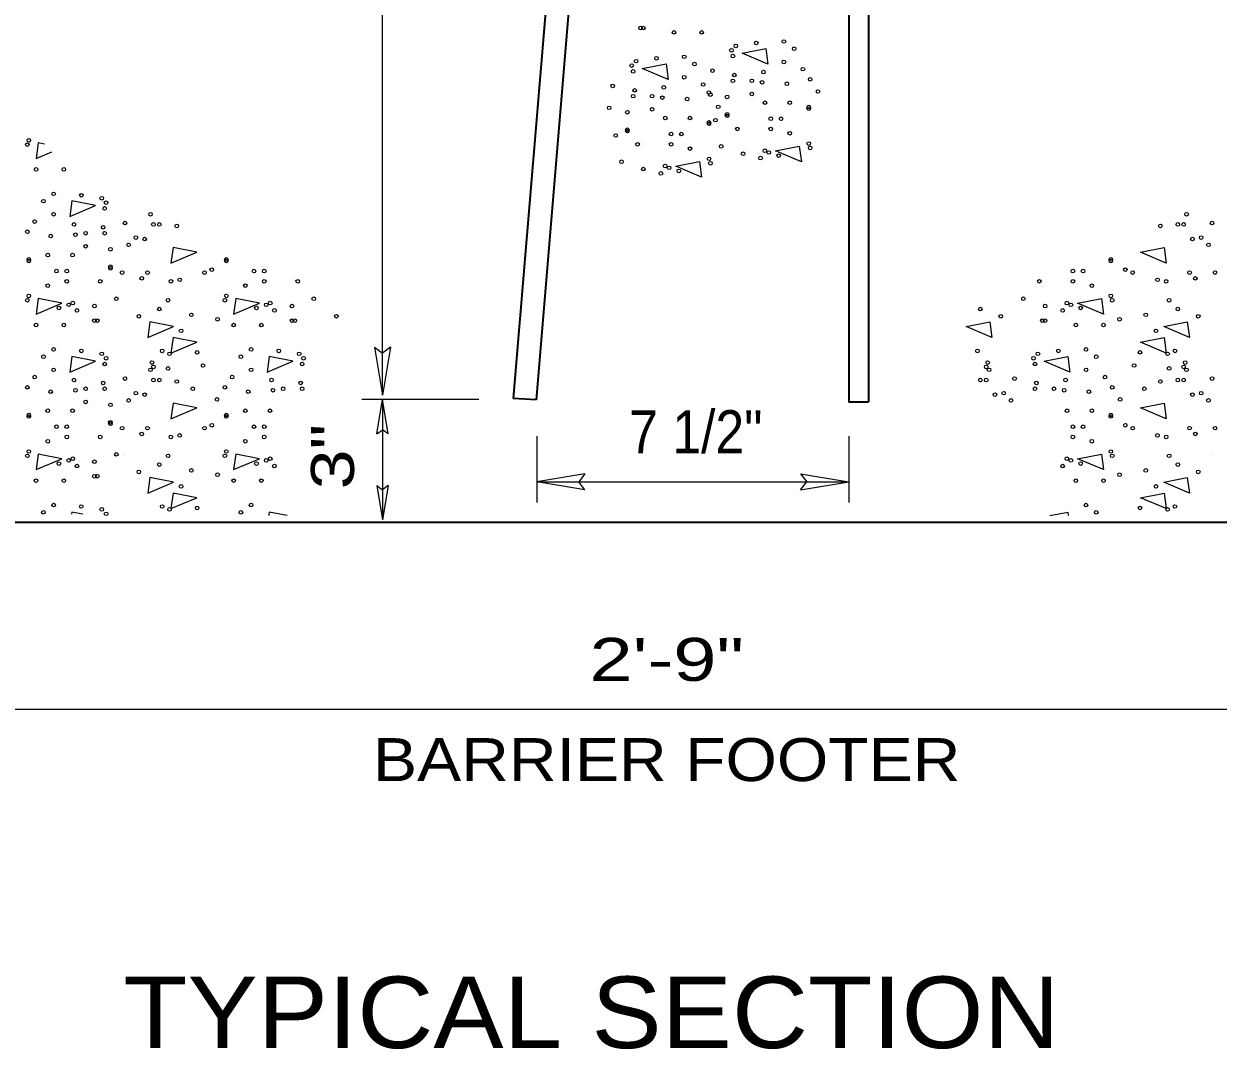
# Model space of a CAD drawing. Extents: x -16.43 to -9.36, y -8.57 to 1.26.
# Drawn here: x -14.571 to -12.904, y -3.734 to -2.302 of the extents above; entities that cross this region are included whole.
import ezdxf
from ezdxf.enums import TextEntityAlignment as Align

# ---------------------------------------------------------------- set-up
doc = ezdxf.new("R2010")
doc.units = 0
doc.header["$LTSCALE"] = 0.024
for name, color, linetype, lineweight in [('1', 7, 'Continuous', 35), ('10', 7, 'Continuous', 13), ('12', 7, 'Continuous', 53), ('6', 7, 'Continuous', 13)]:
    doc.layers.add(name, color=color, linetype=linetype, lineweight=lineweight)

msp = doc.modelspace()

# ---------------------------------------------------------------- linework, layer by layer
at = {"layer": '1'}
for p, q in [((-13.392, 0.00867), (-13.392, -2.83033)), ((-13.69975, -0.56375), (-13.88817, -2.82583)), ((-13.66625, -0.552), (-13.85583, -2.82733)), ((-13.85583, -2.82733), (-13.88817, -2.82583)), ((-14.66667, -2.99817), (-12.69033, -2.99817))]:
    msp.add_line(p, q, dxfattribs=at)
msp.add_lwpolyline([(-13.41917, 0.01217), (-13.41917, -2.83033), (-13.392, -2.83033)], dxfattribs=at)
at = {"layer": '10'}
for p, q in [((-14.0705, -2.82117), (-14.0705, -1.52417)), ((-14.08167, -2.75383), (-14.0705, -2.82117)), ((-14.08167, -2.75383), (-14.0705, -2.76233)), ((-14.05933, -2.75383), (-14.0705, -2.82117)), ((-14.05933, -2.75383), (-14.0705, -2.76233)), ((-13.93617, -2.82717), (-14.09933, -2.82717)), ((-14.0785, -2.87517), (-14.0705, -2.82717)), ((-14.0705, -2.82717), (-14.0705, -2.99517)), ((-14.0625, -2.87517), (-14.0705, -2.82717)), ((-14.0785, -2.87517), (-14.0705, -2.86917)), ((-14.0625, -2.87517), (-14.0705, -2.86917)), ((-13.85517, -2.87833), (-13.85517, -2.97083)), ((-13.4195, -2.87833), (-13.4195, -2.97083)), ((-13.788, -2.93083), (-13.85517, -2.942)), ((-13.788, -2.93083), (-13.79633, -2.942)), ((-13.48667, -2.93083), (-13.4195, -2.942)), ((-13.48667, -2.93083), (-13.47817, -2.942)), ((-14.0785, -2.94717), (-14.0705, -2.99517)), ((-14.0785, -2.94717), (-14.0705, -2.95317)), ((-14.0625, -2.94717), (-14.0705, -2.99517)), ((-14.0625, -2.94717), (-14.0705, -2.95317)), ((-13.85517, -2.942), (-13.4195, -2.942)), ((-13.788, -2.95317), (-13.85517, -2.942)), ((-13.788, -2.95317), (-13.79633, -2.942)), ((-13.48667, -2.95317), (-13.4195, -2.942)), ((-13.48667, -2.95317), (-13.47817, -2.942)), ((-12.69017, -3.26017), (-14.66583, -3.26017))]:
    msp.add_line(p, q, dxfattribs=at)
at = {"layer": '6'}
for points in [[(-13.5685, -2.34317), (-13.53533, -2.33667), (-13.5325, -2.3585)], [(-13.70783, -2.3645), (-13.67467, -2.358), (-13.67183, -2.37983)], [(-13.52167, -2.4795), (-13.48867, -2.473), (-13.48567, -2.49483)], [(-13.661, -2.50083), (-13.62783, -2.49433), (-13.625, -2.51633)], [(-14.4715, -2.556), (-14.5045, -2.5495), (-14.5075, -2.57133)], [(-14.33, -2.621), (-14.36317, -2.61467), (-14.366, -2.6365)], [(-13.01217, -2.621), (-12.97917, -2.61467), (-12.97633, -2.6365)], [(-14.51833, -2.69233), (-14.55133, -2.68583), (-14.55417, -2.70767)], [(-14.2425, -2.69233), (-14.2755, -2.68583), (-14.2785, -2.70767)], [(-13.09983, -2.69233), (-13.06667, -2.68583), (-13.06383, -2.70767)], [(-14.36267, -2.725), (-14.39567, -2.7185), (-14.3985, -2.74033)], [(-13.2555, -2.725), (-13.22233, -2.7185), (-13.2195, -2.74033)], [(-12.97967, -2.725), (-12.94667, -2.7185), (-12.94367, -2.74033)], [(-14.33, -2.74683), (-14.36317, -2.74033), (-14.366, -2.76217)], [(-13.01217, -2.74683), (-12.97917, -2.74033), (-12.97633, -2.76217)], [(-14.4715, -2.77333), (-14.5045, -2.76683), (-14.5075, -2.78867)], [(-14.19567, -2.77333), (-14.22883, -2.76683), (-14.23167, -2.78867)], [(-13.14667, -2.77333), (-13.1135, -2.76683), (-13.11067, -2.78867)], [(-14.33, -2.8385), (-14.36317, -2.832), (-14.366, -2.85383)], [(-13.01217, -2.8385), (-12.97917, -2.832), (-12.97633, -2.85383)], [(-14.51833, -2.90967), (-14.55133, -2.90317), (-14.55417, -2.925)], [(-14.2425, -2.90967), (-14.2755, -2.90317), (-14.2785, -2.925)], [(-13.09983, -2.90967), (-13.06667, -2.90317), (-13.06383, -2.925)], [(-14.36267, -2.94233), (-14.39567, -2.93583), (-14.3985, -2.95767)], [(-12.97967, -2.94233), (-12.94667, -2.93583), (-12.94367, -2.95767)], [(-14.33, -2.96417), (-14.36317, -2.95767), (-14.366, -2.9795)], [(-13.01217, -2.96417), (-12.97917, -2.95767), (-12.97633, -2.9795)]]:
    msp.add_lwpolyline(points, close=True, dxfattribs=at)
for points in [[(-14.54267, -2.47017), (-14.55133, -2.4685), (-14.55417, -2.49033), (-14.53233, -2.481)], [(-14.489, -2.98717), (-14.5045, -2.98417), (-14.505, -2.98717)], [(-14.20383, -2.989), (-14.22883, -2.98417), (-14.22933, -2.98883)], [(-13.1385, -2.989), (-13.1135, -2.98417), (-13.113, -2.98883)]]:
    msp.add_lwpolyline(points, dxfattribs=at)
for centre in [(-13.71035, -2.3081), (-13.70631, -2.3081), (-13.66354, -2.31418), (-13.62486, -2.31418), (-13.57721, -2.33302), (-13.54873, -2.32894), (-13.51004, -2.3269), (-13.49576, -2.3371), (-13.68799, -2.35034), (-13.6493, -2.3483), (-13.58333, -2.33914), (-13.58129, -2.34726), (-13.72259, -2.36055), (-13.72055, -2.36867), (-13.71647, -2.35442), (-13.63502, -2.3585), (-13.60977, -2.36763), (-13.53852, -2.36967), (-13.51004, -2.35542), (-13.48355, -2.36559), (-13.6493, -2.37683), (-13.62282, -2.38699), (-13.58129, -2.38187), (-13.57925, -2.37375), (-13.55481, -2.38187), (-13.54056, -2.38391), (-13.50596, -2.38595), (-13.47339, -2.37983), (-13.74904, -2.38903), (-13.72055, -2.40327), (-13.71851, -2.39515), (-13.69407, -2.40327), (-13.67779, -2.39107), (-13.61482, -2.39815), (-13.61266, -2.40123), (-13.55481, -2.40019), (-13.46247, -2.39675), (-13.75408, -2.41955), (-13.67983, -2.40531), (-13.64522, -2.40735), (-13.60173, -2.41815), (-13.58941, -2.40427), (-13.53648, -2.41243), (-13.50188, -2.41243), (-13.47539, -2.41851), (-13.47539, -2.42055), (-13.72867, -2.42568), (-13.69407, -2.42159), (-13.67575, -2.43384), (-13.64114, -2.43384), (-13.60569, -2.43684), (-13.58941, -2.42872), (-13.58941, -2.43076), (-13.52836, -2.4348), (-13.51408, -2.4348), (-13.72867, -2.45012), (-13.72867, -2.45216), (-13.61466, -2.43992), (-13.61466, -2.44196), (-13.57517, -2.44908), (-13.52836, -2.44908), (-14.56455, -2.46492), (-13.74496, -2.45824), (-13.71443, -2.47048), (-13.66762, -2.4562), (-13.66762, -2.47048), (-13.65334, -2.4562), (-13.50188, -2.45516), (-13.47539, -2.46944), (-14.56655, -2.471), (-13.64114, -2.47656), (-13.59757, -2.47348), (-13.56705, -2.48368), (-13.53672, -2.47952), (-13.53108, -2.48196), (-13.51744, -2.48633), (-13.47339, -2.47552), (-13.73684, -2.49489), (-13.67599, -2.50093), (-13.67034, -2.50337), (-13.61466, -2.49085), (-13.61266, -2.49693), (-13.5426, -2.48977), (-14.55435, -2.50561), (-14.51566, -2.50561), (-13.70631, -2.50509), (-13.68187, -2.51117), (-13.6567, -2.50773), (-14.54419, -2.54994), (-14.52991, -2.53973), (-14.49122, -2.54177), (-14.46273, -2.54585), (-14.45661, -2.55198), (-14.52991, -2.56826), (-14.45865, -2.5601), (-14.3946, -2.56826), (-12.94767, -2.56826), (-14.55639, -2.57842), (-14.50142, -2.5825), (-14.46069, -2.58658), (-14.43017, -2.58046), (-14.39052, -2.5825), (-14.38236, -2.5825), (-14.35796, -2.58454), (-12.98431, -2.58454), (-12.95991, -2.5825), (-12.95175, -2.5825), (-12.9121, -2.58046), (-14.56655, -2.59266), (-14.53399, -2.59878), (-14.49938, -2.59674), (-14.48514, -2.5947), (-14.45865, -2.5947), (-14.41497, -2.60082), (-14.40273, -2.60286), (-12.93955, -2.60286), (-12.92731, -2.60082), (-14.48514, -2.61303), (-14.45053, -2.61711), (-14.42513, -2.61099), (-12.91714, -2.61099), (-14.56455, -2.63135), (-14.56455, -2.63339), (-14.53807, -2.62527), (-14.50346, -2.62527), (-14.28875, -2.63135), (-14.28875, -2.63339), (-13.05353, -2.63135), (-13.05353, -2.63339), (-14.52586, -2.64763), (-14.51158, -2.64763), (-14.45053, -2.64155), (-14.45053, -2.64359), (-14.43425, -2.64967), (-14.39868, -2.64967), (-14.31927, -2.64967), (-14.30907, -2.64563), (-14.25006, -2.64763), (-14.23578, -2.64763), (-13.10649, -2.64763), (-13.09221, -2.64763), (-13.0332, -2.64563), (-13.023, -2.64967), (-12.94359, -2.64967), (-12.90802, -2.64967), (-14.53807, -2.66799), (-14.51158, -2.66191), (-14.46478, -2.66191), (-14.40681, -2.65783), (-14.36608, -2.66191), (-14.35388, -2.65987), (-14.26226, -2.66799), (-14.23578, -2.66191), (-14.18897, -2.66191), (-13.1533, -2.66191), (-13.10649, -2.66191), (-13.08001, -2.66799), (-12.9884, -2.65987), (-12.97619, -2.66191), (-12.93547, -2.65783), (-14.56455, -2.68228), (-14.44237, -2.68632), (-14.28875, -2.68228), (-14.16657, -2.68632), (-13.17571, -2.68632), (-13.05353, -2.68228), (-14.56655, -2.68836), (-14.5225, -2.69916), (-14.50886, -2.6948), (-14.50322, -2.69236), (-14.49734, -2.7026), (-14.4729, -2.69652), (-14.38236, -2.7006), (-14.37016, -2.68836), (-14.29075, -2.68836), (-14.2467, -2.69916), (-14.23306, -2.6948), (-14.22742, -2.69236), (-14.22154, -2.7026), (-14.19709, -2.69652), (-13.23572, -2.7006), (-13.14518, -2.69652), (-13.12074, -2.7026), (-13.11486, -2.69236), (-13.10921, -2.6948), (-13.09557, -2.69916), (-13.05153, -2.68836), (-12.97211, -2.68836), (-12.95991, -2.7006), (-14.4729, -2.71688), (-14.46886, -2.71688), (-14.41089, -2.71076), (-14.33759, -2.70872), (-14.30095, -2.71484), (-14.19709, -2.71688), (-14.19305, -2.71688), (-14.13508, -2.71076), (-13.20719, -2.71076), (-13.14922, -2.71688), (-13.14518, -2.71688), (-13.04132, -2.71484), (-13.00468, -2.70872), (-12.93139, -2.71076), (-14.55435, -2.72296), (-14.51566, -2.72296), (-14.35184, -2.73112), (-14.27855, -2.72296), (-14.23986, -2.72296), (-13.10241, -2.72296), (-13.06373, -2.72296), (-12.99044, -2.73112), (-14.54419, -2.76729), (-14.52991, -2.75709), (-14.49122, -2.75913), (-14.46273, -2.76321), (-14.45661, -2.76933), (-14.37832, -2.75913), (-14.36812, -2.76321), (-14.32943, -2.76117), (-14.26838, -2.76729), (-14.2541, -2.75709), (-14.21542, -2.75913), (-14.18693, -2.76321), (-14.18081, -2.76933), (-13.23976, -2.75913), (-13.16146, -2.76933), (-13.15534, -2.76321), (-13.12686, -2.75913), (-13.08817, -2.75709), (-13.07389, -2.76729), (-13.01284, -2.76117), (-12.97415, -2.76321), (-12.96395, -2.75913), (-14.52991, -2.78561), (-14.45865, -2.77745), (-14.3946, -2.78561), (-14.39256, -2.77541), (-14.39052, -2.78153), (-14.37016, -2.78357), (-14.32131, -2.77949), (-14.2541, -2.78561), (-14.18285, -2.77745), (-13.22755, -2.78153), (-13.22551, -2.77541), (-13.22347, -2.78561), (-13.15942, -2.77745), (-13.08817, -2.78561), (-13.02096, -2.77949), (-12.97211, -2.78357), (-12.95175, -2.78153), (-12.94971, -2.77541), (-12.94767, -2.78561), (-14.55639, -2.79577), (-14.50142, -2.79986), (-14.46069, -2.80394), (-14.43017, -2.79782), (-14.39052, -2.79986), (-14.38236, -2.79986), (-14.35796, -2.8019), (-14.28059, -2.79577), (-14.22562, -2.79986), (-14.18489, -2.80394), (-13.23572, -2.79986), (-13.22755, -2.79986), (-13.18791, -2.79782), (-13.15738, -2.80394), (-13.11666, -2.79986), (-13.06169, -2.79577), (-12.98431, -2.8019), (-12.95991, -2.79986), (-12.95175, -2.79986), (-12.9121, -2.79782), (-14.56655, -2.81002), (-14.53399, -2.81614), (-14.49938, -2.8141), (-14.48514, -2.81206), (-14.45865, -2.81206), (-14.41497, -2.81818), (-14.40273, -2.82022), (-14.33555, -2.81206), (-14.29075, -2.81002), (-14.25818, -2.81614), (-14.22358, -2.8141), (-14.20933, -2.81206), (-14.18285, -2.81206), (-13.21535, -2.82022), (-13.20311, -2.81818), (-13.15942, -2.81206), (-13.13294, -2.81206), (-13.1187, -2.8141), (-13.08409, -2.81614), (-13.05153, -2.81002), (-13.00672, -2.81206), (-12.93955, -2.82022), (-12.92731, -2.81818), (-14.48514, -2.83038), (-14.45053, -2.83446), (-14.42513, -2.82834), (-14.30167, -2.82694), (-13.19295, -2.82834), (-13.0406, -2.82694), (-12.91714, -2.82834), (-14.56455, -2.8487), (-14.56455, -2.85074), (-14.53807, -2.84262), (-14.50346, -2.84262), (-14.28875, -2.8487), (-14.28875, -2.85074), (-14.26226, -2.84262), (-14.22766, -2.84262), (-13.11462, -2.84262), (-13.08001, -2.84262), (-13.05353, -2.8487), (-13.05353, -2.85074), (-14.52586, -2.86499), (-14.51158, -2.86499), (-14.45053, -2.8589), (-14.45053, -2.86095), (-14.43425, -2.86703), (-14.39868, -2.86703), (-14.31927, -2.86703), (-14.30907, -2.86299), (-14.25006, -2.86499), (-14.23578, -2.86499), (-13.10649, -2.86499), (-13.09221, -2.86499), (-13.0332, -2.86299), (-13.023, -2.86703), (-12.94359, -2.86703), (-12.90802, -2.86703), (-14.53807, -2.88535), (-14.51158, -2.87927), (-14.46478, -2.87927), (-14.40681, -2.87519), (-14.36608, -2.87927), (-14.35388, -2.87723), (-14.26226, -2.88535), (-14.23578, -2.87927), (-13.10649, -2.87927), (-13.08001, -2.88535), (-12.9884, -2.87723), (-12.97619, -2.87927), (-12.93547, -2.87519), (-14.56455, -2.89963), (-14.44237, -2.90367), (-14.28875, -2.89963), (-13.05353, -2.89963), (-14.56655, -2.90571), (-14.5225, -2.91651), (-14.50886, -2.91215), (-14.50322, -2.90971), (-14.49734, -2.91995), (-14.4729, -2.91387), (-14.38236, -2.91795), (-14.37016, -2.90571), (-14.29075, -2.90571), (-14.2467, -2.91651), (-14.23306, -2.91215), (-14.22742, -2.90971), (-14.22154, -2.91995), (-13.12074, -2.91995), (-13.11486, -2.90971), (-13.10921, -2.91215), (-13.09557, -2.91651), (-13.05153, -2.90571), (-12.97211, -2.90571), (-12.95991, -2.91795), (-14.4729, -2.93424), (-14.46886, -2.93424), (-14.41089, -2.92812), (-14.33759, -2.92608), (-14.30095, -2.9322), (-13.04132, -2.9322), (-13.00468, -2.92608), (-12.93139, -2.92812), (-14.55435, -2.94032), (-14.51566, -2.94032), (-14.35184, -2.94848), (-14.27855, -2.94032), (-14.23986, -2.94032), (-13.10241, -2.94032), (-13.06373, -2.94032), (-12.99044, -2.94848), (-14.54419, -2.98465), (-14.52991, -2.97444), (-14.49122, -2.97648), (-14.46273, -2.98056), (-14.45661, -2.98669), (-14.37832, -2.97648), (-14.36812, -2.98056), (-14.32943, -2.97852), (-14.26838, -2.98465), (-14.2541, -2.97444), (-13.08817, -2.97444), (-13.07389, -2.98465), (-13.01284, -2.97852), (-12.97415, -2.98056), (-12.96395, -2.97648)]:
    msp.add_circle(centre, 0.00252, dxfattribs=at)
for centre, start, end in [((-14.45129, -2.86003), 266.94086, 266.96201), ((-14.43081, -2.89699), 259.86488, 259.9375), ((-14.43097, -2.89915), 268.76365, 268.77274), ((-12.9113, -2.89915), 271.22726, 271.23635), ((-12.91146, -2.89699), 280.0625, 280.13512)]:
    msp.add_arc(centre, 0.00553, start, end, dxfattribs=at)

# ---------------------------------------------------------------- texts
at = {"layer": '12'}
for s, height, width, p in [('7 1/2"', 0.06001, 0.9, (-13.63304, -2.902)), ('2\'-9"', 0.06001, 1.35, (-13.67367, -3.22008)), ('BARRIER FOOTER', 0.06001, 1.15, (-13.67367, -3.36008)), ('TYPICAL SECTION', 0.1, 1.1, (-13.77892, -3.73308))]:
    msp.add_text(s, height=height, dxfattribs=dict(at, width=width)).set_placement(p, align=Align.CENTER)
at = {"layer": '12', "width": 1.25}
msp.add_text('3"', height=0.06001, rotation=90, dxfattribs=at).set_placement((-14.1105, -2.90683), align=Align.CENTER)

doc.saveas('drawing.dxf')
